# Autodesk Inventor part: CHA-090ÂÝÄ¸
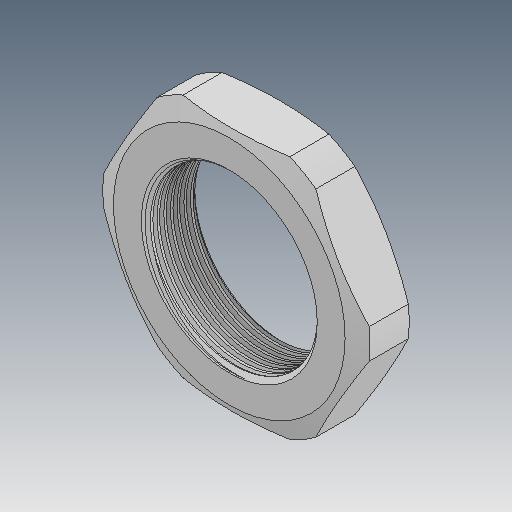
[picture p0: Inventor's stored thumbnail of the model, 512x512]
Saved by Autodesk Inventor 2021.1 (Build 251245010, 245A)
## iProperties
Created: 2019-05
Part Number: CHA-090ÂÝÄ¸
Material: Ogólny
Document SubType Name: Modeling
Designer: user
Density: 1 g/cm^3
Appearance: Domyślna
Author: user
Revision Number: ÈÎºÎ
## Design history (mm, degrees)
feature "¾µÏò1"
node "Bryła1"
